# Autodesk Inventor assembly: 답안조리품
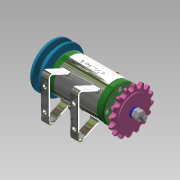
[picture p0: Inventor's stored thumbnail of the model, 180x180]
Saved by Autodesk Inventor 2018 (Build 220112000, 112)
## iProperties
Created: 2021-12
Part Number: 답안조리품
Material: 일반
Document SubType Name: Assembly
Designer: home
Author: home
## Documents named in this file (15)
- C:\Users\home\Desktop\711206V1032\답안조리품.iam
- C:\Users\home\Desktop\711206V1032\본체.ipt
- C:\Users\home\Desktop\711206V1032\커버.ipt
- C:\Users\home\Desktop\711206V1032\베어링 6002.ipt
- C:\Users\home\Desktop\711206V1032\축.ipt
- C:\Users\home\Desktop\711206V1032\오일 실 15 x 25 x 7.ipt
- C:\Users\home\Desktop\711206V1032\V벨트풀리.ipt
- C:\Users\home\Desktop\711206V1032\키 3 x 3.ipt
- C:\Users\home\Desktop\711206V1032\스프로킷.ipt
- C:\Users\home\Desktop\711206V1032\스프링와셔 8.ipt
- C:\Users\home\Desktop\711206V1032\너트 M8.ipt
- C:\Users\home\Desktop\711206V1032\와셔 6 x 11.5.ipt
- C:\Users\home\Desktop\711206V1032\볼트 M6 x 8.ipt
- C:\Users\home\Desktop\711206V1032\니플 M6 x 0.75.ipt
- C:\Users\home\Desktop\711206V1032\볼트 M4 x 12.ipt
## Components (11 placed, 3 different names)
1. KS B 2023 6002 - 15 x 32 x 9:1
2. KS B 2023 6002 - 15 x 32 x 9:2
3. V벨트풀리:1
4. ISO 4762 M4 x 12:5
5. ISO 4762 M4 x 12:6
6. ISO 4762 M4 x 12:7
7. ISO 4762 M4 x 12:8
8. ISO 4762 M4 x 12:1
9. ISO 4762 M4 x 12:2
10. ISO 4762 M4 x 12:3
11. ISO 4762 M4 x 12:4
